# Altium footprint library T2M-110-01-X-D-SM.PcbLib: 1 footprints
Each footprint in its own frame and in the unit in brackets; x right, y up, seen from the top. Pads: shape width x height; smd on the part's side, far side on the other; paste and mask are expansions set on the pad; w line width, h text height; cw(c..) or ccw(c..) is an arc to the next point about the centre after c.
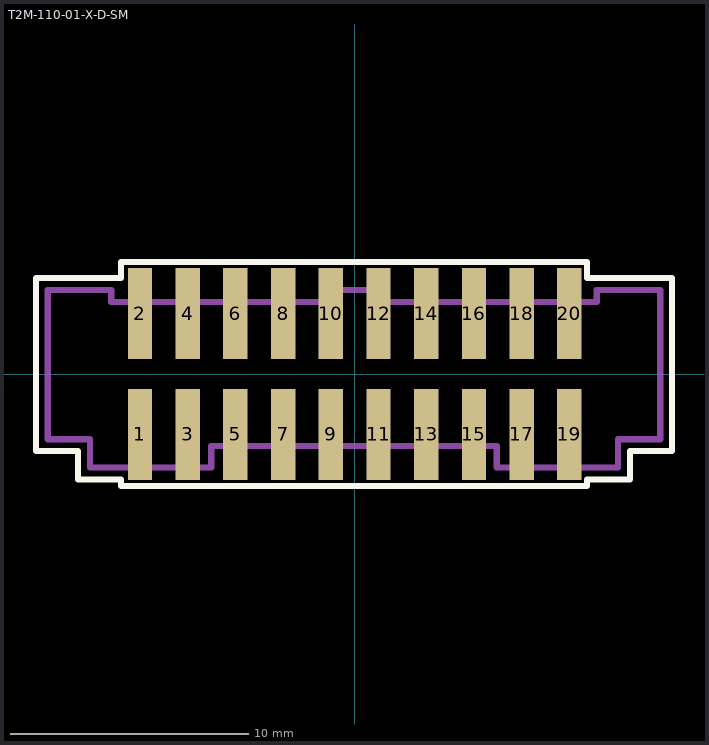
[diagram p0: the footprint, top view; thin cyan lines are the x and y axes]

## T2M-110-01-X-D-SM [mm]
pads (20):
  rect 1.02x3.8 smd mask+0.05: 1(-9,-2.535) 2(-9,2.535) 3(-7,-2.535) 4(-7,2.535) 5(-5,-2.535) 6(-5,2.535) 7(-3,-2.535) 8(-3,2.535) 9(-1,-2.535) 10(-1,2.535) 11(1,-2.535) 12(1,2.535) 13(3,-2.535) 14(3,2.535) 15(5,-2.535) 16(5,2.535) 17(7,-2.535) 18(7,2.535) 19(9,-2.535) 20(9,2.535)
Top Overlay:
  lines w0.254: -13.365,-3.235 -13.365,4.023 -9.79,4.023 -9.79,4.691 9.734,4.691 9.734,4.023 13.309,4.023 13.309,-3.235 11.537,-3.235 11.537,-4.415 9.734,-4.415 9.734,-4.691 -9.79,-4.691 -9.79,-4.415 -11.592,-4.415 -11.592,-3.235 -13.365,-3.235
Mechanical 1:
  lines w0.254: -12.865,-2.735 -12.865,3.523 -10.203,3.523 -10.203,3.015 -1.298,3.015 -1.298,3.523 1.242,3.523 1.242,3.015 10.148,3.015 10.148,3.523 12.809,3.523 12.809,-2.735 11.037,-2.735 11.037,-3.915 5.956,-3.915 5.956,-3.015 -6.011,-3.015 -6.011,-3.915 -11.092,-3.915 -11.092,-2.735 -12.865,-2.735
  text "J1" at -0.497,-0.508 h0.76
